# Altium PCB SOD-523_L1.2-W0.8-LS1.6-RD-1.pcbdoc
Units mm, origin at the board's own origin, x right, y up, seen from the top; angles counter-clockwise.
Board outline 14.57 x 13.8 mm, 2 copper layers (Top Layer, Bottom Layer), stack 0 mm thick; 1 components, 0 nets, 2 pads, 0 vias.
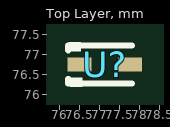
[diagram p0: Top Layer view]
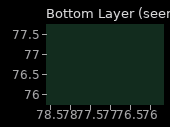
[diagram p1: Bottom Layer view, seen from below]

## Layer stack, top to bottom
Top Layer: signal copper (thickness not stored)
Bottom Layer: signal copper (thickness not stored)

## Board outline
84.42,69.85 69.85,69.85 69.85,83.654 84.42,83.654

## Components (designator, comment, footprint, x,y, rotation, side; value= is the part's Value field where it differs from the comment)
U? "" SOD-523_L1.2-W0.8-LS1.6-RD-1 77.135,76.752 r0 top

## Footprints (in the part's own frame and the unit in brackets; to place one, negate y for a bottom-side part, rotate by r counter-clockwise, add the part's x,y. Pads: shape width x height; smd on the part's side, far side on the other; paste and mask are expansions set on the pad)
SOD-523_L1.2-W0.8-LS1.6-RD-1 [mm]
  rect 0.6x0.36 smd: 1(-0.635,0) 2(0.635,0)
  silkscreen extent -0.91,-0.55 0.68,0.55

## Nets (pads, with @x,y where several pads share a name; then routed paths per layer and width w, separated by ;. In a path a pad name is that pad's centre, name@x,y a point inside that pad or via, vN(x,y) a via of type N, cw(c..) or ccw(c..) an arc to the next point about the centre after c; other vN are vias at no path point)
pads on no net: U?.1 U?.2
